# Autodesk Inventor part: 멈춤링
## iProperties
IsCustomPart: 1
Company: 한국ATC센터
Created: 2014-10
Part Number: 멈춤링
Material: 강, 연강
Description: 리테이닝 링(C형)
Document SubType Name: Modeling
Standard: KS B 1336
Designer: 한국ATC센터
Standards Organization: KS
Language: ko-KR
Size Designation: 25 x 1.2
Categories: <MemberInstance><Categories><Category DisplayName="샤프트 부품" InternalName="7f7aeb1f-a693-4053-b835-cee3144e0d98" Mnemonic="SHFT"><Category DisplayName="써클립" Inter
Density: 7.86 g/cm^3
Mass: 2.3429 g
Surface Area: 7.2498 cm^2
Volume: 0.298079 cm^3
Author: KYOUNG IL JANG
Revision Number: 1
